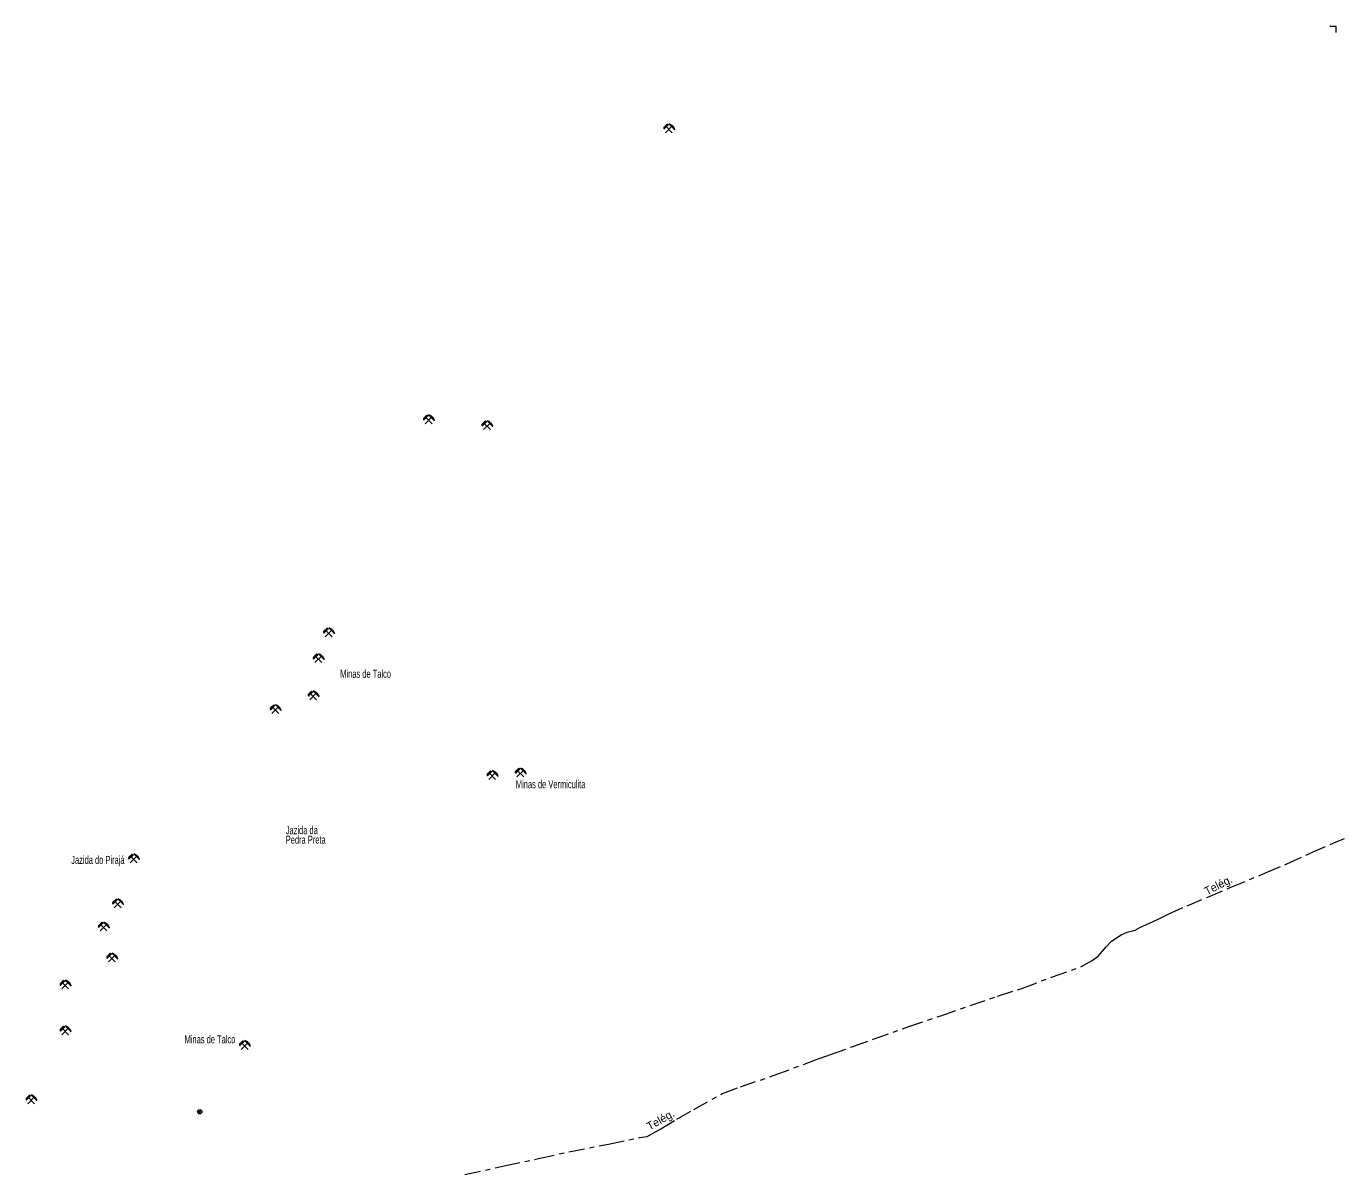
# Model space of a CAD drawing. Extents: x 175.9 to 230.5, y 8394.8 to 8450.8.
# Drawn here: x 203.76 to 230.11, y 8427.88 to 8450.83 of the extents above; entities that cross this region are included whole.
import ezdxf
from ezdxf.enums import TextEntityAlignment as Align

# ---------------------------------------------------------------- set-up
doc = ezdxf.new("R2010")
doc.units = 0
doc.header["$LTSCALE"] = 0.064
doc.header["$PDMODE"] = 32
doc.header["$PDSIZE"] = 0.032
doc.linetypes.add('DOT_DASHED', pattern=[7.7, 5, -1.2, 0.3, -1.2])
for name, color, linetype, lineweight in [('47', 7, 'Continuous', 13), ('49', 7, 'Continuous', 25), ('57', 7, 'DOT_DASHED', 13), ('63', 7, 'Continuous', 13)]:
    doc.layers.add(name, color=color, linetype=linetype, lineweight=lineweight)
doc.layers.add('61', color=7, linetype='Continuous')

msp = doc.modelspace()

# ---------------------------------------------------------------- hatches: boundary and pattern name
at = {"layer": '49'}
for points in [[(216.57, 8448.8769), (216.5894, 8448.8577), (216.51, 8448.7785), (216.5062, 8448.7881), (216.5062, 8448.7977), (216.5082, 8448.8113), (216.514, 8448.8209)], [(216.603, 8448.8809), (216.6202, 8448.8731), (216.6376, 8448.8635), (216.6512, 8448.8557), (216.6628, 8448.8461), (216.6784, 8448.8325), (216.6918, 8448.8131), (216.6996, 8448.7997), (216.7074, 8448.7841), (216.715, 8448.7687)], [(211.7672, 8443.0602), (211.7866, 8443.041), (211.7072, 8442.9618), (211.7034, 8442.9714), (211.7034, 8442.981), (211.7054, 8442.9946), (211.7112, 8443.0042)], [(211.8002, 8443.0642), (211.8174, 8443.0564), (211.8348, 8443.0468), (211.8484, 8443.039), (211.86, 8443.0294), (211.8756, 8443.0158), (211.889, 8442.9964), (211.8968, 8442.983), (211.9046, 8442.9674), (211.9122, 8442.952)], [(212.9343, 8442.9429), (212.9537, 8442.9237), (212.8743, 8442.8445), (212.8705, 8442.8541), (212.8705, 8442.8637), (212.8725, 8442.8773), (212.8783, 8442.8869)], [(212.9673, 8442.9469), (212.9845, 8442.9391), (213.0019, 8442.9295), (213.0155, 8442.9217), (213.0271, 8442.9121), (213.0427, 8442.8985), (213.0561, 8442.8791), (213.0639, 8442.8657), (213.0717, 8442.8501), (213.0793, 8442.8347)], [(209.7709, 8438.8028), (209.7903, 8438.7836), (209.7109, 8438.7044), (209.7071, 8438.714), (209.7071, 8438.7236), (209.7091, 8438.7372), (209.7149, 8438.7468)], [(209.8039, 8438.8068), (209.8211, 8438.799), (209.8385, 8438.7894), (209.8521, 8438.7816), (209.8637, 8438.772), (209.8793, 8438.7584), (209.8927, 8438.739), (209.9005, 8438.7256), (209.9083, 8438.71), (209.9159, 8438.6946)], [(209.5652, 8438.2851), (209.5846, 8438.2659), (209.5052, 8438.1867), (209.5014, 8438.1963), (209.5014, 8438.2059), (209.5034, 8438.2195), (209.5092, 8438.2291)], [(209.5982, 8438.2891), (209.6154, 8438.2813), (209.6328, 8438.2717), (209.6464, 8438.2639), (209.658, 8438.2543), (209.6736, 8438.2407), (209.687, 8438.2213), (209.6948, 8438.2079), (209.7026, 8438.1923), (209.7102, 8438.1769)], [(209.4599, 8437.5422), (209.4793, 8437.523), (209.3999, 8437.4438), (209.3961, 8437.4534), (209.3961, 8437.463), (209.3981, 8437.4766), (209.4039, 8437.4862)], [(209.4929, 8437.5462), (209.5101, 8437.5384), (209.5275, 8437.5288), (209.5411, 8437.521), (209.5527, 8437.5114), (209.5683, 8437.4978), (209.5817, 8437.4784), (209.5895, 8437.465), (209.5973, 8437.4494), (209.6049, 8437.434)], [(208.7035, 8437.2679), (208.7229, 8437.2487), (208.6435, 8437.1695), (208.6397, 8437.1791), (208.6397, 8437.1887), (208.6417, 8437.2023), (208.6475, 8437.2119)], [(208.7365, 8437.2719), (208.7537, 8437.2641), (208.7711, 8437.2545), (208.7847, 8437.2467), (208.7963, 8437.2371), (208.8119, 8437.2235), (208.8253, 8437.2041), (208.8331, 8437.1907), (208.8409, 8437.1751), (208.8485, 8437.1597)], [(213.0391, 8435.9499), (213.0585, 8435.9307), (212.9791, 8435.8515), (212.9753, 8435.8611), (212.9753, 8435.8707), (212.9773, 8435.8843), (212.9831, 8435.8939)], [(213.0721, 8435.9539), (213.0893, 8435.9461), (213.1067, 8435.9365), (213.1203, 8435.9287), (213.1319, 8435.9191), (213.1475, 8435.9055), (213.1609, 8435.8861), (213.1687, 8435.8727), (213.1765, 8435.8571), (213.1841, 8435.8417)], [(213.6006, 8436.0002), (213.62, 8435.981), (213.5406, 8435.9018), (213.5368, 8435.9114), (213.5368, 8435.921), (213.5388, 8435.9346), (213.5446, 8435.9442)], [(213.6336, 8436.0042), (213.6508, 8435.9964), (213.6682, 8435.9868), (213.6818, 8435.979), (213.6934, 8435.9694), (213.709, 8435.9558), (213.7224, 8435.9364), (213.7302, 8435.923), (213.738, 8435.9074), (213.7456, 8435.892)], [(205.874, 8434.2851), (205.8934, 8434.2659), (205.814, 8434.1867), (205.8102, 8434.1963), (205.8102, 8434.2059), (205.8122, 8434.2195), (205.818, 8434.2291)], [(205.907, 8434.2891), (205.9242, 8434.2813), (205.9416, 8434.2717), (205.9552, 8434.2639), (205.9668, 8434.2543), (205.9824, 8434.2407), (205.9958, 8434.2213), (206.0036, 8434.2079), (206.0114, 8434.1923), (206.019, 8434.1769)], [(205.5542, 8433.3858), (205.5736, 8433.3666), (205.4942, 8433.2874), (205.4904, 8433.297), (205.4904, 8433.3066), (205.4924, 8433.3202), (205.4982, 8433.3298)], [(205.5872, 8433.3898), (205.6044, 8433.382), (205.6218, 8433.3724), (205.6354, 8433.3646), (205.647, 8433.355), (205.6626, 8433.3414), (205.676, 8433.322), (205.6838, 8433.3086), (205.6916, 8433.293), (205.6992, 8433.2776)], [(205.2705, 8432.9212), (205.2899, 8432.902), (205.2105, 8432.8228), (205.2067, 8432.8324), (205.2067, 8432.842), (205.2087, 8432.8556), (205.2145, 8432.8652)], [(205.3035, 8432.9252), (205.3207, 8432.9174), (205.3381, 8432.9078), (205.3517, 8432.9), (205.3633, 8432.8904), (205.3789, 8432.8768), (205.3923, 8432.8574), (205.4001, 8432.844), (205.4079, 8432.8284), (205.4155, 8432.813)], [(205.4372, 8432.3016), (205.4566, 8432.2824), (205.3772, 8432.2032), (205.3734, 8432.2128), (205.3734, 8432.2224), (205.3754, 8432.236), (205.3812, 8432.2456)], [(205.4702, 8432.3056), (205.4874, 8432.2978), (205.5048, 8432.2882), (205.5184, 8432.2804), (205.53, 8432.2708), (205.5456, 8432.2572), (205.559, 8432.2378), (205.5668, 8432.2244), (205.5746, 8432.2088), (205.5822, 8432.1934)], [(204.5047, 8431.7617), (204.5241, 8431.7425), (204.4447, 8431.6633), (204.4409, 8431.6729), (204.4409, 8431.6825), (204.4429, 8431.6961), (204.4487, 8431.7057)], [(204.5377, 8431.7657), (204.5549, 8431.7579), (204.5723, 8431.7483), (204.5859, 8431.7405), (204.5975, 8431.7309), (204.6131, 8431.7173), (204.6265, 8431.6979), (204.6343, 8431.6845), (204.6421, 8431.6689), (204.6497, 8431.6535)], [(204.5041, 8430.8461), (204.5235, 8430.8269), (204.4441, 8430.7477), (204.4403, 8430.7573), (204.4403, 8430.7669), (204.4423, 8430.7805), (204.4481, 8430.7901)], [(204.5371, 8430.8501), (204.5543, 8430.8423), (204.5717, 8430.8327), (204.5853, 8430.8249), (204.5969, 8430.8153), (204.6125, 8430.8017), (204.6259, 8430.7823), (204.6337, 8430.7689), (204.6415, 8430.7533), (204.6491, 8430.7379)], [(208.0899, 8430.5537), (208.1093, 8430.5345), (208.0299, 8430.4553), (208.0261, 8430.4649), (208.0261, 8430.4745), (208.0281, 8430.4881), (208.0339, 8430.4977)], [(208.1229, 8430.5577), (208.1401, 8430.5499), (208.1575, 8430.5403), (208.1711, 8430.5325), (208.1827, 8430.5229), (208.1983, 8430.5093), (208.2117, 8430.4899), (208.2195, 8430.4765), (208.2273, 8430.4609), (208.2349, 8430.4455)], [(203.8242, 8429.468), (203.8436, 8429.4488), (203.7642, 8429.3696), (203.7604, 8429.3792), (203.7604, 8429.3888), (203.7624, 8429.4024), (203.7682, 8429.412)], [(203.8572, 8429.472), (203.8744, 8429.4642), (203.8918, 8429.4546), (203.9054, 8429.4468), (203.917, 8429.4372), (203.9326, 8429.4236), (203.946, 8429.4042), (203.9538, 8429.3908), (203.9616, 8429.3752), (203.9692, 8429.3598)]]:
    msp.add_hatch(color=256, dxfattribs=at).paths.add_polyline_path(points)

# ---------------------------------------------------------------- linework, layer by layer
at = {"layer": '47'}
msp.add_circle((207.2256, 8429.1333), 0.043, dxfattribs=at)
msp.add_point((207.226, 8429.1331), dxfattribs=at)
at = {"layer": '49'}
for p, q in [((216.5332, 8448.7029), (216.657, 8448.8267)), ((216.6706, 8448.7029), (216.5526, 8448.8209)), ((211.7304, 8442.8862), (211.8542, 8443.01)), ((211.8678, 8442.8862), (211.7498, 8443.0042)), ((212.8975, 8442.7689), (213.0213, 8442.8927)), ((213.0349, 8442.7689), (212.9169, 8442.8869)), ((209.7341, 8438.6288), (209.8579, 8438.7526)), ((209.8715, 8438.6288), (209.7535, 8438.7468)), ((209.5284, 8438.1111), (209.6522, 8438.2349)), ((209.6658, 8438.1111), (209.5478, 8438.2291)), ((209.4231, 8437.3682), (209.5469, 8437.492)), ((209.5605, 8437.3682), (209.4425, 8437.4862)), ((208.6667, 8437.0939), (208.7905, 8437.2177)), ((208.8041, 8437.0939), (208.6861, 8437.2119)), ((213.0023, 8435.7759), (213.1261, 8435.8997)), ((213.1397, 8435.7759), (213.0217, 8435.8939)), ((213.5638, 8435.8262), (213.6876, 8435.95)), ((213.7012, 8435.8262), (213.5832, 8435.9442)), ((205.8372, 8434.1111), (205.961, 8434.2349)), ((205.9746, 8434.1111), (205.8566, 8434.2291)), ((205.5174, 8433.2118), (205.6412, 8433.3356)), ((205.6548, 8433.2118), (205.5368, 8433.3298)), ((205.2337, 8432.7472), (205.3575, 8432.871)), ((205.3711, 8432.7472), (205.2531, 8432.8652)), ((205.4004, 8432.1276), (205.5242, 8432.2514)), ((205.5378, 8432.1276), (205.4198, 8432.2456)), ((204.4679, 8431.5877), (204.5917, 8431.7115)), ((204.6053, 8431.5877), (204.4873, 8431.7057)), ((204.4673, 8430.6721), (204.5911, 8430.7959)), ((204.6047, 8430.6721), (204.4867, 8430.7901)), ((208.0531, 8430.3797), (208.1769, 8430.5035)), ((208.1905, 8430.3797), (208.0725, 8430.4977)), ((203.7874, 8429.294), (203.9112, 8429.4178)), ((203.9248, 8429.294), (203.8068, 8429.412))]:
    msp.add_line(p, q, dxfattribs=at)
for points in [[(216.57, 8448.8769), (216.5894, 8448.8577), (216.51, 8448.7785), (216.5062, 8448.7881), (216.5062, 8448.7977), (216.5082, 8448.8113), (216.514, 8448.8209)], [(216.603, 8448.8809), (216.6202, 8448.8731), (216.6376, 8448.8635), (216.6512, 8448.8557), (216.6628, 8448.8461), (216.6784, 8448.8325), (216.6918, 8448.8131), (216.6996, 8448.7997), (216.7074, 8448.7841), (216.715, 8448.7687)], [(211.7672, 8443.0602), (211.7866, 8443.041), (211.7072, 8442.9618), (211.7034, 8442.9714), (211.7034, 8442.981), (211.7054, 8442.9946), (211.7112, 8443.0042)], [(211.8002, 8443.0642), (211.8174, 8443.0564), (211.8348, 8443.0468), (211.8484, 8443.039), (211.86, 8443.0294), (211.8756, 8443.0158), (211.889, 8442.9964), (211.8968, 8442.983), (211.9046, 8442.9674), (211.9122, 8442.952)], [(212.9343, 8442.9429), (212.9537, 8442.9237), (212.8743, 8442.8445), (212.8705, 8442.8541), (212.8705, 8442.8637), (212.8725, 8442.8773), (212.8783, 8442.8869)], [(212.9673, 8442.9469), (212.9845, 8442.9391), (213.0019, 8442.9295), (213.0155, 8442.9217), (213.0271, 8442.9121), (213.0427, 8442.8985), (213.0561, 8442.8791), (213.0639, 8442.8657), (213.0717, 8442.8501), (213.0793, 8442.8347)], [(209.7709, 8438.8028), (209.7903, 8438.7836), (209.7109, 8438.7044), (209.7071, 8438.714), (209.7071, 8438.7236), (209.7091, 8438.7372), (209.7149, 8438.7468)], [(209.8039, 8438.8068), (209.8211, 8438.799), (209.8385, 8438.7894), (209.8521, 8438.7816), (209.8637, 8438.772), (209.8793, 8438.7584), (209.8927, 8438.739), (209.9005, 8438.7256), (209.9083, 8438.71), (209.9159, 8438.6946)], [(209.5652, 8438.2851), (209.5846, 8438.2659), (209.5052, 8438.1867), (209.5014, 8438.1963), (209.5014, 8438.2059), (209.5034, 8438.2195), (209.5092, 8438.2291)], [(209.5982, 8438.2891), (209.6154, 8438.2813), (209.6328, 8438.2717), (209.6464, 8438.2639), (209.658, 8438.2543), (209.6736, 8438.2407), (209.687, 8438.2213), (209.6948, 8438.2079), (209.7026, 8438.1923), (209.7102, 8438.1769)], [(209.4599, 8437.5422), (209.4793, 8437.523), (209.3999, 8437.4438), (209.3961, 8437.4534), (209.3961, 8437.463), (209.3981, 8437.4766), (209.4039, 8437.4862)], [(209.4929, 8437.5462), (209.5101, 8437.5384), (209.5275, 8437.5288), (209.5411, 8437.521), (209.5527, 8437.5114), (209.5683, 8437.4978), (209.5817, 8437.4784), (209.5895, 8437.465), (209.5973, 8437.4494), (209.6049, 8437.434)], [(208.7035, 8437.2679), (208.7229, 8437.2487), (208.6435, 8437.1695), (208.6397, 8437.1791), (208.6397, 8437.1887), (208.6417, 8437.2023), (208.6475, 8437.2119)], [(208.7365, 8437.2719), (208.7537, 8437.2641), (208.7711, 8437.2545), (208.7847, 8437.2467), (208.7963, 8437.2371), (208.8119, 8437.2235), (208.8253, 8437.2041), (208.8331, 8437.1907), (208.8409, 8437.1751), (208.8485, 8437.1597)], [(213.0391, 8435.9499), (213.0585, 8435.9307), (212.9791, 8435.8515), (212.9753, 8435.8611), (212.9753, 8435.8707), (212.9773, 8435.8843), (212.9831, 8435.8939)], [(213.0721, 8435.9539), (213.0893, 8435.9461), (213.1067, 8435.9365), (213.1203, 8435.9287), (213.1319, 8435.9191), (213.1475, 8435.9055), (213.1609, 8435.8861), (213.1687, 8435.8727), (213.1765, 8435.8571), (213.1841, 8435.8417)], [(213.6006, 8436.0002), (213.62, 8435.981), (213.5406, 8435.9018), (213.5368, 8435.9114), (213.5368, 8435.921), (213.5388, 8435.9346), (213.5446, 8435.9442)], [(213.6336, 8436.0042), (213.6508, 8435.9964), (213.6682, 8435.9868), (213.6818, 8435.979), (213.6934, 8435.9694), (213.709, 8435.9558), (213.7224, 8435.9364), (213.7302, 8435.923), (213.738, 8435.9074), (213.7456, 8435.892)], [(205.874, 8434.2851), (205.8934, 8434.2659), (205.814, 8434.1867), (205.8102, 8434.1963), (205.8102, 8434.2059), (205.8122, 8434.2195), (205.818, 8434.2291)], [(205.907, 8434.2891), (205.9242, 8434.2813), (205.9416, 8434.2717), (205.9552, 8434.2639), (205.9668, 8434.2543), (205.9824, 8434.2407), (205.9958, 8434.2213), (206.0036, 8434.2079), (206.0114, 8434.1923), (206.019, 8434.1769)], [(205.5542, 8433.3858), (205.5736, 8433.3666), (205.4942, 8433.2874), (205.4904, 8433.297), (205.4904, 8433.3066), (205.4924, 8433.3202), (205.4982, 8433.3298)], [(205.5872, 8433.3898), (205.6044, 8433.382), (205.6218, 8433.3724), (205.6354, 8433.3646), (205.647, 8433.355), (205.6626, 8433.3414), (205.676, 8433.322), (205.6838, 8433.3086), (205.6916, 8433.293), (205.6992, 8433.2776)], [(205.2705, 8432.9212), (205.2899, 8432.902), (205.2105, 8432.8228), (205.2067, 8432.8324), (205.2067, 8432.842), (205.2087, 8432.8556), (205.2145, 8432.8652)], [(205.3035, 8432.9252), (205.3207, 8432.9174), (205.3381, 8432.9078), (205.3517, 8432.9), (205.3633, 8432.8904), (205.3789, 8432.8768), (205.3923, 8432.8574), (205.4001, 8432.844), (205.4079, 8432.8284), (205.4155, 8432.813)], [(205.4372, 8432.3016), (205.4566, 8432.2824), (205.3772, 8432.2032), (205.3734, 8432.2128), (205.3734, 8432.2224), (205.3754, 8432.236), (205.3812, 8432.2456)], [(205.4702, 8432.3056), (205.4874, 8432.2978), (205.5048, 8432.2882), (205.5184, 8432.2804), (205.53, 8432.2708), (205.5456, 8432.2572), (205.559, 8432.2378), (205.5668, 8432.2244), (205.5746, 8432.2088), (205.5822, 8432.1934)], [(204.5047, 8431.7617), (204.5241, 8431.7425), (204.4447, 8431.6633), (204.4409, 8431.6729), (204.4409, 8431.6825), (204.4429, 8431.6961), (204.4487, 8431.7057)], [(204.5377, 8431.7657), (204.5549, 8431.7579), (204.5723, 8431.7483), (204.5859, 8431.7405), (204.5975, 8431.7309), (204.6131, 8431.7173), (204.6265, 8431.6979), (204.6343, 8431.6845), (204.6421, 8431.6689), (204.6497, 8431.6535)], [(204.5041, 8430.8461), (204.5235, 8430.8269), (204.4441, 8430.7477), (204.4403, 8430.7573), (204.4403, 8430.7669), (204.4423, 8430.7805), (204.4481, 8430.7901)], [(204.5371, 8430.8501), (204.5543, 8430.8423), (204.5717, 8430.8327), (204.5853, 8430.8249), (204.5969, 8430.8153), (204.6125, 8430.8017), (204.6259, 8430.7823), (204.6337, 8430.7689), (204.6415, 8430.7533), (204.6491, 8430.7379)], [(208.0899, 8430.5537), (208.1093, 8430.5345), (208.0299, 8430.4553), (208.0261, 8430.4649), (208.0261, 8430.4745), (208.0281, 8430.4881), (208.0339, 8430.4977)], [(208.1229, 8430.5577), (208.1401, 8430.5499), (208.1575, 8430.5403), (208.1711, 8430.5325), (208.1827, 8430.5229), (208.1983, 8430.5093), (208.2117, 8430.4899), (208.2195, 8430.4765), (208.2273, 8430.4609), (208.2349, 8430.4455)], [(203.8242, 8429.468), (203.8436, 8429.4488), (203.7642, 8429.3696), (203.7604, 8429.3792), (203.7604, 8429.3888), (203.7624, 8429.4024), (203.7682, 8429.412)], [(203.8572, 8429.472), (203.8744, 8429.4642), (203.8918, 8429.4546), (203.9054, 8429.4468), (203.917, 8429.4372), (203.9326, 8429.4236), (203.946, 8429.4042), (203.9538, 8429.3908), (203.9616, 8429.3752), (203.9692, 8429.3598)]]:
    msp.add_lwpolyline(points, close=True, dxfattribs=at)
at = {"layer": '57'}
msp.add_lwpolyline([(212.5256, 8427.8769), (213.3131, 8428.0498), (213.9994, 8428.1996), (214.6011, 8428.3329), (215.3925, 8428.4864), (216.0209, 8428.6178), (216.1669, 8428.6387), (216.4398, 8428.7933), (216.7635, 8428.9881), (217.0984, 8429.1758), (217.671, 8429.4987), (218.0332, 8429.6313), (218.7082, 8429.8635), (219.5314, 8430.1686), (219.8352, 8430.2809), (220.2777, 8430.4382), (220.6883, 8430.5849), (221.3758, 8430.8303), (222.0361, 8431.0544), (223.1732, 8431.4446), (223.6555, 8431.5997), (224.2518, 8431.8244), (224.8368, 8432.0304), (225.0621, 8432.1542), (225.1803, 8432.2459), (225.3453, 8432.4294), (225.4503, 8432.5418), (225.6416, 8432.6691), (225.7616, 8432.7253), (225.9191, 8432.7627), (226.0166, 8432.8152), (226.2792, 8432.9388), (226.4104, 8432.9949), (226.5829, 8433.0848), (226.9593, 8433.2522), (227.3719, 8433.4245), (227.8219, 8433.6155), (228.5293, 8433.9085), (228.9531, 8434.0882), (229.4332, 8434.3092), (229.8926, 8434.5059), (230.1083, 8434.5981)], dxfattribs=at)
at = {"layer": '63'}
msp.add_lwpolyline([(229.9361, 8450.7058), (229.9361, 8450.829), (229.8147, 8450.829)], dxfattribs=at)

# ---------------------------------------------------------------- texts
at = {"layer": '61', "width": 0.7}
for s, p in [('Minas de Talco', (210.0332, 8437.8081)), ('Minas de Vermiculita', (213.5438, 8435.6006)), ('Jazida da', (208.9444, 8434.6821)), ('Pedra Preta', (208.9444, 8434.4921)), ('Jazida do Pirajá', (204.6576, 8434.0882)), ('Minas de Talco', (206.9219, 8430.5016))]:
    msp.add_text(s, height=0.16, dxfattribs=at).set_placement(p)
at = {"layer": '61'}
for rotation, p in [(26.811, (227.62, 8433.5945)), (29.729, (216.4742, 8428.9048))]:
    msp.add_text('Telég.', height=0.16, rotation=rotation, dxfattribs=at).set_placement(p, align=Align.CENTER)

doc.saveas('drawing.dxf')
